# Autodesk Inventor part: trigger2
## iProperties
Created: 2010-11
Part Number: trigger2
Document SubType Name: Modeling
Designer: ROBERT
Density: 1 g/cm^3
Author: ROBERT
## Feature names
1. Extrusion1
2. Extrusion2
3. Extrusion3
4. Extrusion4
5. Fillet1
6. TaggingFeature1
